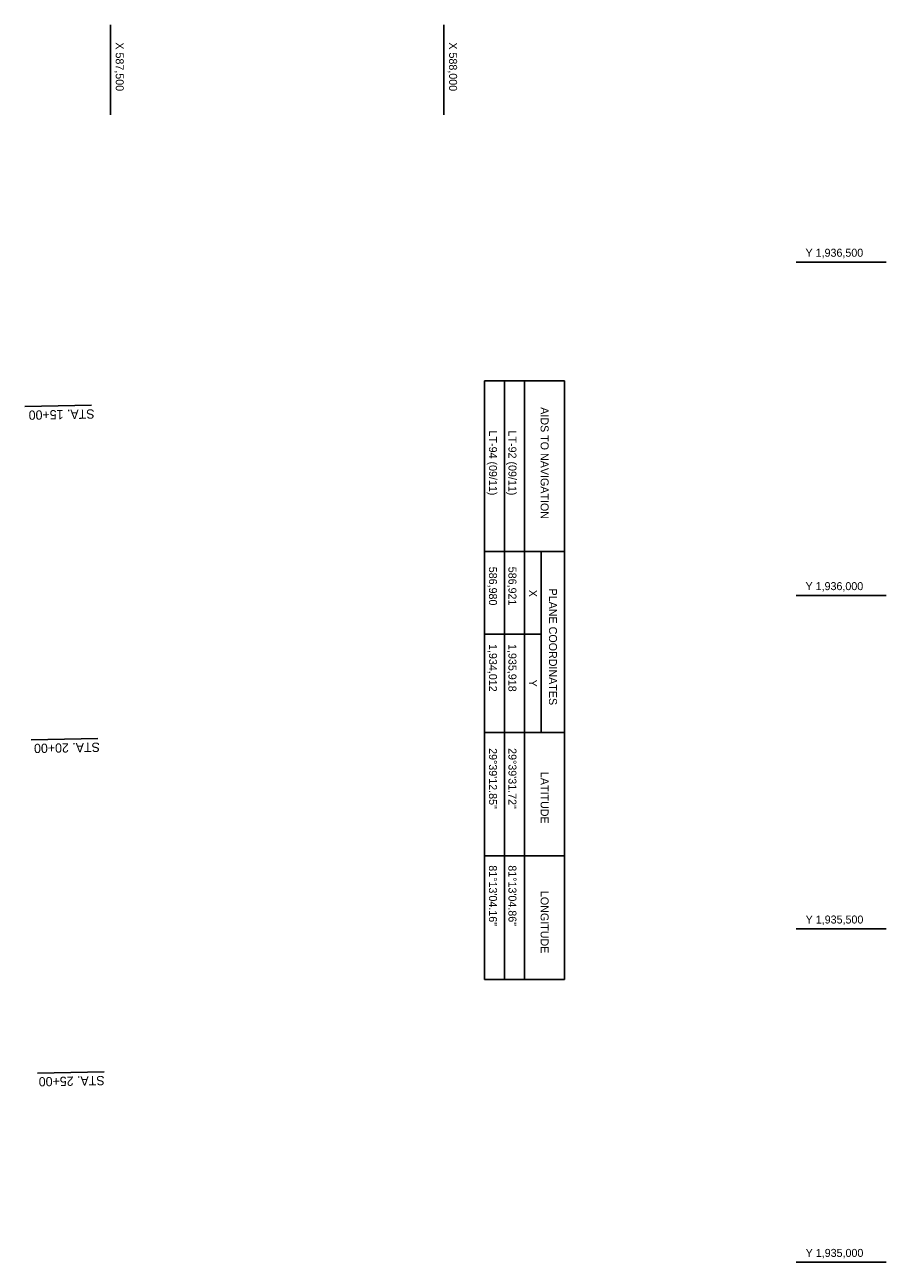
# Model space of a CAD drawing. Extents: x 585414 to 588664, y 1932755 to 1936856.
# Drawn here: x 587372 to 588664, y 1935000 to 1936856 of the extents above; entities that cross this region are included whole.
import ezdxf

# ---------------------------------------------------------------- set-up
doc = ezdxf.new("R2010")
doc.units = 0
for name, color, linetype in [('V-ANNO-KEYN', 7, 'Continuous'), ('V-ANNO-MASK', 7, 'Continuous'), ('V-COMM-OVHD', 7, 'Continuous'), ('V-COMM-OVHD-IDEN', 7, 'Continuous')]:
    doc.layers.add(name, color=color, linetype=linetype)

msp = doc.modelspace()

# ---------------------------------------------------------------- linework, layer by layer
at = {"layer": 'V-ANNO-KEYN'}
for p, q in [((587500, 1936855.9), (587500, 1936720.9)), ((588000, 1936855.9), (588000, 1936720.9)), ((588528.7, 1936500), (588663.7, 1936500)), ((588528.7, 1936000), (588663.7, 1936000)), ((588528.7, 1935500), (588663.7, 1935500)), ((588528.7, 1935000), (588663.7, 1935000))]:
    msp.add_line(p, q, dxfattribs=at)
at = {"layer": 'V-COMM-OVHD'}
for p, q in [((587371.5, 1936283.5), (587471.5, 1936285.4)), ((587381.1, 1935783.6), (587481, 1935785.5)), ((587390.6, 1935283.6), (587490.6, 1935285.5))]:
    msp.add_line(p, q, dxfattribs=at)
at = {"layer": 'V-COMM-OVHD-IDEN'}
for p, q in [((588181.3, 1936322), (588061.3, 1936322)), ((588061.3, 1936322), (588061.3, 1935424.1)), ((588091.3, 1936322), (588091.3, 1935424.1)), ((588121.3, 1936322), (588121.3, 1935424.1)), ((588181.3, 1936322), (588181.3, 1935424.1)), ((588181.3, 1936065.7), (588061.3, 1936065.7)), ((588146.3, 1936065.7), (588146.3, 1935794.7)), ((588146.3, 1935942.1), (588061.3, 1935942.1)), ((588181.3, 1935794.7), (588061.3, 1935794.7)), ((588181.3, 1935609.4), (588061.3, 1935609.4)), ((588061.3, 1935424.1), (588181.3, 1935424.1))]:
    msp.add_line(p, q, dxfattribs=at)

# ---------------------------------------------------------------- texts
at = {"layer": 'V-ANNO-MASK'}
for s, p in [('X 587,500', (587508, 1936829.5)), ('X 588,000', (588008, 1936829.5))]:
    msp.add_text(s, height=12, rotation=270, dxfattribs=at).set_placement(p)
for s, p in [('Y 1,936,500', (588542.6, 1936508)), ('Y 1,936,000', (588542.6, 1936008)), ('Y 1,935,500', (588542.8, 1935508)), ('Y 1,935,000', (588542.8, 1935008))]:
    msp.add_text(s, height=12, dxfattribs=at).set_placement(p)
at = {"layer": 'V-COMM-OVHD'}
for s, p in [('STA. 15+00', (587476.1, 1936279.2)), ('STA. 20+00', (587484.1, 1935779.4)), ('STA. 25+00', (587491.2, 1935279.5))]:
    msp.add_text(s, height=13.92, rotation=181.0918, dxfattribs=at).set_placement(p)
at = {"layer": 'V-COMM-OVHD-IDEN'}
for s, p in [('AIDS TO NAVIGATION', (588145.3, 1936282.3)), ('LT-94 (09/11)                        586,980             1,934,012                   29°39\'12.85"                   81°13\'04.16"', (588067.8, 1936247.3)), ('LT-92 (09/11)                        586,921             1,935,918                   29°39\'31.72"                   81°13\'04.86"', (588097, 1936247.3)), ('X', (588127.8, 1936008.5)), ('PLANE COORDINATES', (588157.8, 1936010.3)), ('Y', (588127.8, 1935873.7)), ('LATITUDE', (588145.3, 1935735.4)), ('LONGITUDE', (588145.3, 1935556.9))]:
    msp.add_text(s, height=12, rotation=270, dxfattribs=at).set_placement(p)

doc.saveas('drawing.dxf')
